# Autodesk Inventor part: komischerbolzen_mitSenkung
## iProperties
Category: Vorlagendatei
Company: KAME engineering
Created: 2011-07
Part Number: komischerbolzen_mitSenkung
Material: S355J2 (1.0577)
Description: =<Beschreibung Zeile 1>
Document SubType Name: Modeling
Designer: Öller
Stock Number: =<B>x<D>
Density: 7.85 g/cm^3
Mass: 5336.58 g
Surface Area: 587.045 cm^2
Volume: 679.819 cm^3
CAD-System: Autodesk Inventor
Telefon Ersteller: 2474
Telefon Prüfer: 2474
L: 1
B: 1
D: 1
G_L: =<L>
Bezeichnung_Englisch: =<Beschreibung Zeile 2>
Title: Einzelteilvorlage
Subject: Vorlage
Author: Öller
Keywords: Einzelteile
Comments: Erstellt am 30.06.2009 Mayrhofer Ronald Basis: VAI Konstruktionsrichtlinien Kap.5 rev. 2 (18.05.2007)
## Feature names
1. Extrusion1
2. Bohrung1 [Hole]
3. Bohrung2 [Hole]
4. Fase14 [Chamfer]
5. Fase15 [Chamfer]
6. Extrusion2
7. Spiegeln1 [Mirror]
8. Fase24 [Chamfer]
